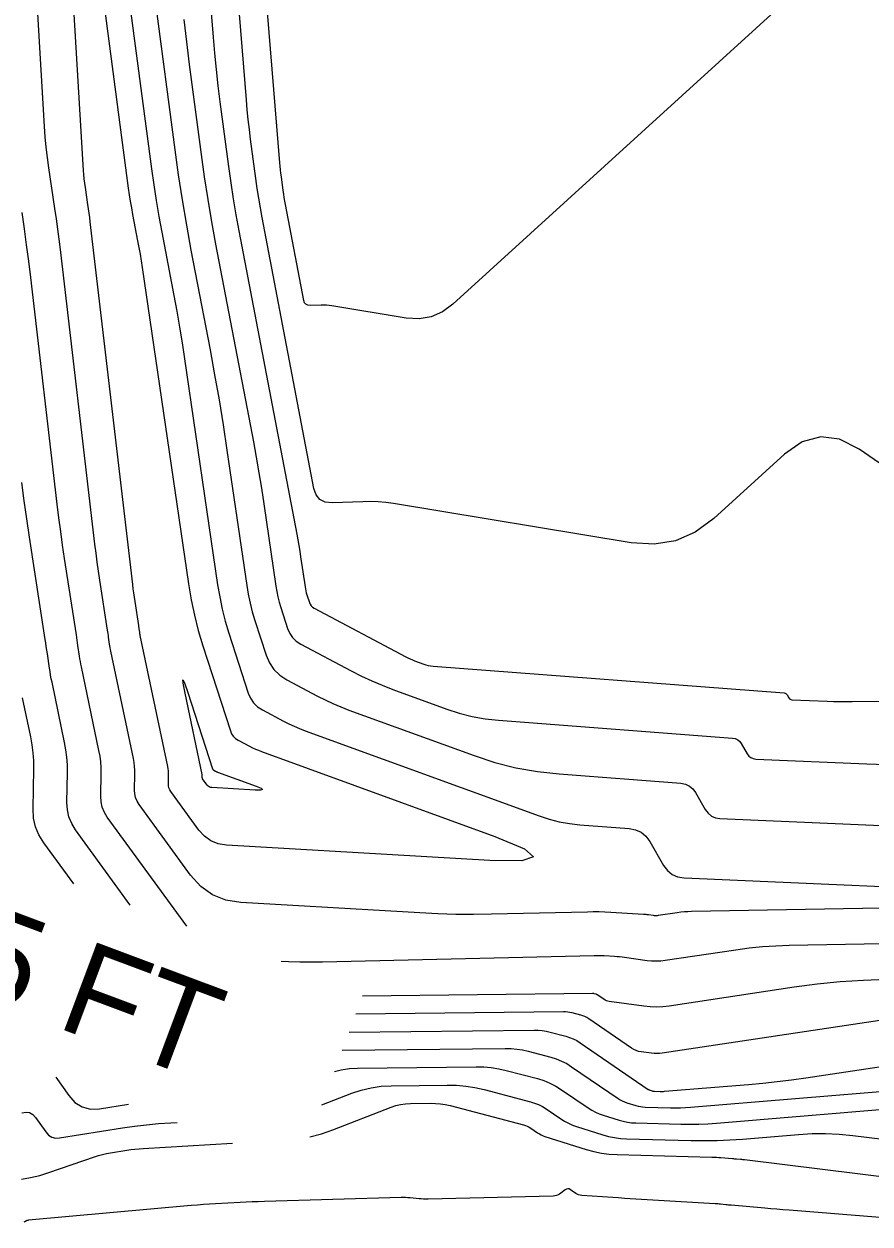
# Model space of a CAD drawing. Extents: x 1768942 to 1774819, y 723037 to 732099.
# Drawn here: x 1770893.1 to 1770947.3, y 724474.6 to 724551.5 of the extents above; entities that cross this region are included whole.
import ezdxf

# ---------------------------------------------------------------- set-up
doc = ezdxf.new("R2010")
doc.units = 0
doc.layers.add('R_Contour Annot', color=7, linetype='Continuous')
doc.layers.add('R_Contours', color=7, linetype='Continuous')

msp = doc.modelspace()

# ---------------------------------------------------------------- linework, layer by layer
at = {"layer": 'R_Contours'}
for points in [[(1770944.996, 724555.826), (1770920.559, 724533.556), (1770919.893, 724533.065), (1770919.175, 724532.754), (1770918.403, 724532.624), (1770917.577, 724532.674), (1770912.81, 724533.462), (1770912.637, 724533.486), (1770912.463, 724533.501), (1770912.289, 724533.508), (1770912.115, 724533.505), (1770911.416, 724533.479), (1770911.259, 724533.494), (1770911.137, 724533.555), (1770911.051, 724533.659), (1770911, 724533.809), (1770909.826, 724539.957), (1770909.786, 724540.179), (1770909.748, 724540.4), (1770909.714, 724540.623), (1770909.683, 724540.845), (1770909.565, 724541.738), (1770909.537, 724541.961), (1770909.512, 724542.184), (1770909.489, 724542.408), (1770909.469, 724542.632), (1770907.695, 724564.314)], [(1770962.968, 724513.006), (1770946.615, 724524.278), (1770945.369, 724524.91), (1770944.155, 724525.066), (1770942.974, 724524.747), (1770941.824, 724523.953), (1770937.292, 724519.822), (1770936.111, 724518.95), (1770934.836, 724518.398), (1770933.466, 724518.167), (1770932.001, 724518.257), (1770916.755, 724520.775), (1770916.267, 724520.843), (1770915.778, 724520.887), (1770915.287, 724520.905), (1770914.794, 724520.899), (1770912.82, 724520.823), (1770912.377, 724520.867), (1770912.034, 724521.037), (1770911.791, 724521.333), (1770911.648, 724521.756), (1770908.334, 724539.112), (1770908.219, 724539.736), (1770908.113, 724540.362), (1770908.017, 724540.99), (1770907.929, 724541.618), (1770907.596, 724544.137), (1770907.517, 724544.767), (1770907.445, 724545.398), (1770907.382, 724546.029), (1770907.326, 724546.662), (1770905.976, 724563.16)], [(1770904.257, 724562.006), (1770905.183, 724550.692), (1770905.275, 724549.651), (1770905.379, 724548.611), (1770905.497, 724547.573), (1770905.627, 724546.536), (1770906.175, 724542.391), (1770906.319, 724541.356), (1770906.478, 724540.324), (1770906.652, 724539.294), (1770906.841, 724538.266), (1770910.556, 724518.816), (1770910.623, 724518.453), (1770910.686, 724518.091), (1770910.745, 724517.727), (1770910.801, 724517.363), (1770911.084, 724515.432), (1770911.105, 724515.305), (1770911.131, 724515.179), (1770911.163, 724515.055), (1770911.2, 724514.932), (1770911.359, 724514.442), (1770911.407, 724514.327), (1770911.475, 724514.228), (1770911.561, 724514.144), (1770911.665, 724514.076), (1770917.546, 724510.953), (1770917.684, 724510.883), (1770917.824, 724510.818), (1770917.966, 724510.758), (1770918.11, 724510.703), (1770918.692, 724510.491), (1770918.838, 724510.443), (1770918.987, 724510.406), (1770919.138, 724510.379), (1770919.291, 724510.362), (1770941.82, 724508.634), (1770941.876, 724508.623), (1770941.924, 724508.601), (1770941.965, 724508.567), (1770941.998, 724508.521), (1770942.117, 724508.313), (1770942.151, 724508.268), (1770942.192, 724508.234), (1770942.24, 724508.213), (1770942.296, 724508.205), (1770944.567, 724508.107), (1770944.965, 724508.092), (1770945.364, 724508.083), (1770945.763, 724508.079), (1770946.161, 724508.081), (1770964.2, 724508.274)], [(1770897.085, 724561.182), (1770899.75, 724541.013), (1770899.81, 724540.586), (1770899.875, 724540.161), (1770899.947, 724539.736), (1770900.025, 724539.312), (1770900.348, 724537.62), (1770900.426, 724537.196), (1770900.5, 724536.772), (1770900.57, 724536.347), (1770900.634, 724535.921), (1770903.607, 724515.624), (1770903.776, 724514.616), (1770903.987, 724513.618), (1770904.24, 724512.63), (1770904.533, 724511.651), (1770906.294, 724506.203), (1770906.373, 724506.018), (1770906.482, 724505.858), (1770906.621, 724505.722), (1770906.789, 724505.612), (1770907.525, 724505.222), (1770907.71, 724505.127), (1770907.898, 724505.04), (1770908.09, 724504.959), (1770908.284, 724504.884), (1770923.25, 724499.44), (1770925.149, 724498.645), (1770925.729, 724498.123), (1770924.99, 724497.873), (1770922.931, 724497.895), (1770906.04, 724498.88), (1770905.514, 724498.965), (1770905.045, 724499.153), (1770904.633, 724499.446), (1770904.277, 724499.843), (1770902.479, 724502.313), (1770902.408, 724502.428), (1770902.358, 724502.549), (1770902.329, 724502.678), (1770902.321, 724502.813), (1770902.331, 724503.366), (1770902.33, 724503.504), (1770902.321, 724503.641), (1770902.304, 724503.778), (1770902.279, 724503.913), (1770900.517, 724512.319), (1770900.507, 724512.372), (1770900.497, 724512.426), (1770900.488, 724512.479), (1770900.479, 724512.533), (1770900.448, 724512.749), (1770900.44, 724512.803), (1770900.432, 724512.857), (1770900.424, 724512.91), (1770900.415, 724512.964), (1770900.179, 724514.499), (1770900.138, 724514.773), (1770900.099, 724515.047), (1770900.064, 724515.321), (1770900.03, 724515.596), (1770897.308, 724538.849), (1770897.275, 724539.124), (1770897.239, 724539.399), (1770897.201, 724539.674), (1770897.161, 724539.948), (1770896.995, 724541.045), (1770896.956, 724541.319), (1770896.924, 724541.594), (1770896.898, 724541.87), (1770896.879, 724542.146), (1770895.708, 724561.836)], [(1770952.924, 724494.92), (1770935.868, 724494.619), (1770935.638, 724494.611), (1770935.408, 724494.595), (1770935.179, 724494.572), (1770934.95, 724494.542), (1770933.738, 724494.36), (1770933.659, 724494.351), (1770933.581, 724494.348), (1770933.502, 724494.35), (1770933.423, 724494.358), (1770933.108, 724494.402), (1770933.029, 724494.412), (1770932.95, 724494.421), (1770932.871, 724494.428), (1770932.791, 724494.434), (1770930.694, 724494.561), (1770930.318, 724494.58), (1770929.942, 724494.591), (1770929.565, 724494.594), (1770929.189, 724494.589), (1770923.044, 724494.446), (1770921.894, 724494.43), (1770920.745, 724494.439), (1770919.597, 724494.47), (1770918.448, 724494.526), (1770906.975, 724495.195), (1770906.01, 724495.35), (1770905.149, 724495.696), (1770904.393, 724496.233), (1770903.741, 724496.961), (1770900.442, 724501.492), (1770900.312, 724501.704), (1770900.22, 724501.927), (1770900.167, 724502.163), (1770900.152, 724502.41), (1770900.17, 724503.425), (1770900.167, 724503.678), (1770900.151, 724503.93), (1770900.12, 724504.18), (1770900.075, 724504.43), (1770898.631, 724511.318), (1770898.608, 724511.43), (1770898.588, 724511.541), (1770898.569, 724511.654), (1770898.551, 724511.766), (1770898.485, 724512.217), (1770898.469, 724512.329), (1770898.452, 724512.442), (1770898.435, 724512.555), (1770898.418, 724512.667), (1770897.923, 724515.874), (1770897.838, 724516.446), (1770897.758, 724517.019), (1770897.682, 724517.593), (1770897.613, 724518.167), (1770895.4, 724537.067), (1770895.32, 724537.725), (1770895.235, 724538.383), (1770895.144, 724539.039), (1770895.048, 724539.695), (1770894.651, 724542.317), (1770894.559, 724542.974), (1770894.482, 724543.631), (1770894.42, 724544.291), (1770894.373, 724544.952), (1770893.488, 724559.836)], [(1770899.278, 724557.086), (1770901.239, 724542.242), (1770901.382, 724541.221), (1770901.539, 724540.204), (1770901.71, 724539.188), (1770901.896, 724538.175), (1770902.669, 724534.127), (1770902.857, 724533.114), (1770903.034, 724532.099), (1770903.199, 724531.083), (1770903.354, 724530.064), (1770905.476, 724515.576), (1770905.609, 724514.789), (1770905.773, 724514.009), (1770905.97, 724513.236), (1770906.2, 724512.471), (1770907.441, 724508.631), (1770907.586, 724508.291), (1770907.786, 724507.997), (1770908.041, 724507.749), (1770908.35, 724507.547), (1770909.7, 724506.83), (1770910.04, 724506.657), (1770910.385, 724506.496), (1770910.736, 724506.347), (1770911.092, 724506.211), (1770926.095, 724500.753), (1770926.735, 724500.545), (1770927.384, 724500.381), (1770928.043, 724500.262), (1770928.711, 724500.188), (1770931.871, 724499.946), (1770932.284, 724499.868), (1770932.642, 724499.704), (1770932.944, 724499.451), (1770933.192, 724499.112), (1770934.071, 724497.579), (1770934.318, 724497.241), (1770934.621, 724496.995), (1770934.98, 724496.839), (1770935.393, 724496.775), (1770957.86, 724495.806)], [(1770901.471, 724552.99), (1770902.729, 724543.47), (1770902.954, 724541.856), (1770903.202, 724540.246), (1770903.473, 724538.64), (1770903.767, 724537.037), (1770904.99, 724530.634), (1770905.287, 724529.032), (1770905.567, 724527.427), (1770905.829, 724525.819), (1770906.074, 724524.208), (1770907.346, 724515.528), (1770907.441, 724514.961), (1770907.559, 724514.399), (1770907.701, 724513.842), (1770907.867, 724513.291), (1770908.588, 724511.06), (1770908.799, 724510.564), (1770909.09, 724510.136), (1770909.461, 724509.775), (1770909.911, 724509.481), (1770911.874, 724508.439), (1770912.369, 724508.187), (1770912.872, 724507.953), (1770913.382, 724507.736), (1770913.9, 724507.538), (1770921.921, 724504.62), (1770923.256, 724504.185), (1770924.611, 724503.843), (1770925.986, 724503.595), (1770927.381, 724503.441), (1770935.187, 724502.842), (1770935.481, 724502.787), (1770935.736, 724502.669), (1770935.951, 724502.49), (1770936.127, 724502.248), (1770936.753, 724501.157), (1770936.929, 724500.917), (1770937.145, 724500.741), (1770937.4, 724500.631), (1770937.694, 724500.585), (1770951.996, 724499.968)], [(1770903.313, 724551.825), (1770903.477, 724550.379), (1770903.658, 724548.935), (1770904.421, 724543.165), (1770904.622, 724541.723), (1770904.843, 724540.286), (1770905.086, 724538.851), (1770905.348, 724537.42), (1770907.77, 724524.743), (1770907.953, 724523.752), (1770908.126, 724522.759), (1770908.289, 724521.764), (1770908.44, 724520.767), (1770909.215, 724515.48), (1770909.273, 724515.133), (1770909.345, 724514.789), (1770909.432, 724514.449), (1770909.533, 724514.112), (1770909.967, 724512.77), (1770910.101, 724512.456), (1770910.285, 724512.184), (1770910.52, 724511.955), (1770910.806, 724511.769), (1770914.049, 724510.047), (1770914.699, 724509.717), (1770915.358, 724509.409), (1770916.028, 724509.125), (1770916.709, 724508.864), (1770920.167, 724507.606), (1770920.978, 724507.342), (1770921.801, 724507.134), (1770922.636, 724506.984), (1770923.484, 724506.89), (1770938.504, 724505.738), (1770938.678, 724505.705), (1770938.83, 724505.635), (1770938.958, 724505.528), (1770939.063, 724505.385), (1770939.435, 724504.735), (1770939.54, 724504.592), (1770939.668, 724504.488), (1770939.82, 724504.422), (1770939.995, 724504.395), (1770947.102, 724504.088), (1770948.349, 724504.043)], [(1770903.495, 724493.68), (1770898.404, 724500.672), (1770898.215, 724500.979), (1770898.082, 724501.305), (1770898.004, 724501.647), (1770897.983, 724502.008), (1770898.009, 724503.484), (1770898.005, 724503.853), (1770897.981, 724504.219), (1770897.936, 724504.583), (1770897.87, 724504.946), (1770896.745, 724510.317), (1770896.71, 724510.487), (1770896.679, 724510.657), (1770896.65, 724510.828), (1770896.623, 724510.999), (1770896.523, 724511.685), (1770896.498, 724511.856), (1770896.472, 724512.028), (1770896.446, 724512.199), (1770896.42, 724512.37), (1770895.668, 724517.249), (1770895.538, 724518.12), (1770895.416, 724518.992), (1770895.301, 724519.865), (1770895.195, 724520.739), (1770893.492, 724535.285), (1770893.366, 724536.326), (1770893.231, 724537.366), (1770893.087, 724538.405), (1770892.934, 724539.442)], [(1770899.874, 724495.035), (1770896.367, 724499.852), (1770896.119, 724500.255), (1770895.943, 724500.682), (1770895.842, 724501.132), (1770895.814, 724501.605), (1770895.848, 724503.544), (1770895.843, 724504.027), (1770895.811, 724504.508), (1770895.752, 724504.986), (1770895.666, 724505.462), (1770894.858, 724509.317), (1770894.812, 724509.545), (1770894.77, 724509.773), (1770894.731, 724510.002), (1770894.695, 724510.232), (1770894.56, 724511.153), (1770894.526, 724511.383), (1770894.492, 724511.613), (1770894.457, 724511.843), (1770894.422, 724512.073), (1770893.413, 724518.624), (1770893.238, 724519.794), (1770893.074, 724520.964), (1770892.92, 724522.136)], [(1770896.253, 724496.39), (1770894.33, 724499.032), (1770894.022, 724499.531), (1770893.805, 724500.06), (1770893.679, 724500.617), (1770893.644, 724501.202), (1770893.69, 724503.76), (1770893.684, 724504.28), (1770893.65, 724504.798), (1770893.586, 724505.312), (1770893.494, 724505.824), (1770892.972, 724508.316)], [(1770954.156, 724492.65), (1770942.124, 724492.437), (1770941.266, 724492.408), (1770940.41, 724492.351), (1770939.556, 724492.265), (1770938.704, 724492.151), (1770934.188, 724491.473), (1770933.895, 724491.44), (1770933.602, 724491.428), (1770933.308, 724491.437), (1770933.015, 724491.467), (1770931.576, 724491.668), (1770931.414, 724491.689), (1770931.252, 724491.706), (1770931.09, 724491.721), (1770930.927, 724491.733), (1770930.275, 724491.772), (1770930.112, 724491.78), (1770929.949, 724491.785), (1770929.786, 724491.786), (1770929.623, 724491.784), (1770912.208, 724491.377), (1770911.481, 724491.368), (1770910.755, 724491.373), (1770910.029, 724491.393), (1770909.544, 724491.416)], [(1770948.381, 724490.256), (1770946.894, 724490.206), (1770945.411, 724490.106), (1770943.933, 724489.958), (1770942.458, 724489.761), (1770934.427, 724488.555), (1770934.025, 724488.509), (1770933.623, 724488.492), (1770933.22, 724488.505), (1770932.818, 724488.546), (1770930.59, 724488.857), (1770930.498, 724488.875), (1770930.411, 724488.903), (1770930.327, 724488.941), (1770930.248, 724488.99), (1770929.826, 724489.278), (1770929.803, 724489.292), (1770929.779, 724489.305), (1770929.754, 724489.315), (1770929.728, 724489.323), (1770929.623, 724489.35), (1770929.596, 724489.356), (1770929.57, 724489.36), (1770929.543, 724489.363), (1770929.516, 724489.363), (1770914.772, 724489.199)], [(1770948.368, 724487.695), (1770933.978, 724485.533), (1770933.811, 724485.514), (1770933.644, 724485.507), (1770933.477, 724485.512), (1770933.31, 724485.529), (1770932.642, 724485.623), (1770932.478, 724485.655), (1770932.321, 724485.705), (1770932.172, 724485.773), (1770932.029, 724485.86), (1770929.277, 724487.742), (1770929.156, 724487.817), (1770929.031, 724487.881), (1770928.9, 724487.934), (1770928.765, 724487.976), (1770928.212, 724488.12), (1770928.074, 724488.151), (1770927.934, 724488.173), (1770927.793, 724488.186), (1770927.651, 724488.189), (1770914.339, 724488.041)], [(1770913.905, 724486.882), (1770925.785, 724487.015), (1770926.043, 724487.009), (1770926.298, 724486.986), (1770926.551, 724486.947), (1770926.802, 724486.89), (1770927.801, 724486.628), (1770928.047, 724486.553), (1770928.283, 724486.458), (1770928.51, 724486.342), (1770928.727, 724486.206), (1770933.099, 724483.216), (1770933.128, 724483.198), (1770933.158, 724483.182), (1770933.189, 724483.169), (1770933.221, 724483.157), (1770933.351, 724483.116), (1770933.384, 724483.107), (1770933.418, 724483.1), (1770933.451, 724483.096), (1770933.485, 724483.094), (1770933.853, 724483.084), (1770933.926, 724483.083), (1770933.998, 724483.084), (1770934.071, 724483.087), (1770934.143, 724483.092), (1770939.526, 724483.537), (1770940.447, 724483.62), (1770941.365, 724483.72), (1770942.282, 724483.834), (1770943.197, 724483.964), (1770954.598, 724485.676)], [(1770913.472, 724485.724), (1770923.92, 724485.84), (1770924.292, 724485.832), (1770924.662, 724485.799), (1770925.028, 724485.742), (1770925.391, 724485.66), (1770926.838, 724485.281), (1770927.193, 724485.172), (1770927.535, 724485.034), (1770927.863, 724484.867), (1770928.178, 724484.67), (1770931.17, 724482.624), (1770931.298, 724482.543), (1770931.431, 724482.473), (1770931.569, 724482.412), (1770931.711, 724482.361), (1770932.292, 724482.178), (1770932.438, 724482.138), (1770932.586, 724482.108), (1770932.735, 724482.088), (1770932.887, 724482.079), (1770934.521, 724482.035), (1770934.844, 724482.031), (1770935.166, 724482.036), (1770935.489, 724482.049), (1770935.811, 724482.072), (1770956.013, 724483.74)], [(1770912.965, 724484.37), (1770913.406, 724484.476), (1770913.928, 724484.552), (1770914.458, 724484.581), (1770922.055, 724484.666), (1770922.542, 724484.655), (1770923.026, 724484.612), (1770923.505, 724484.537), (1770923.981, 724484.429), (1770925.982, 724483.906), (1770926.394, 724483.78), (1770926.791, 724483.619), (1770927.172, 724483.425), (1770927.538, 724483.197), (1770929.241, 724482.032), (1770929.468, 724481.888), (1770929.704, 724481.763), (1770929.949, 724481.655), (1770930.202, 724481.565), (1770931.233, 724481.24), (1770931.492, 724481.168), (1770931.754, 724481.115), (1770932.02, 724481.08), (1770932.288, 724481.064), (1770935.189, 724480.987), (1770935.762, 724480.98), (1770936.334, 724480.988), (1770936.907, 724481.012), (1770937.479, 724481.051), (1770948.457, 724481.958)], [(1770895.104, 724484.007), (1770895.934, 724482.819), (1770896.33, 724482.377), (1770896.791, 724482.089), (1770897.318, 724481.956), (1770897.911, 724481.978), (1770899.754, 724482.267)], [(1770912.161, 724482.221), (1770914.074, 724482.963), (1770914.691, 724483.171), (1770915.319, 724483.322), (1770915.958, 724483.416), (1770916.608, 724483.452), (1770920.19, 724483.492), (1770920.792, 724483.479), (1770921.39, 724483.425), (1770921.982, 724483.332), (1770922.57, 724483.199), (1770925.533, 724482.424), (1770925.802, 724482.342), (1770926.061, 724482.237), (1770926.31, 724482.11), (1770926.549, 724481.961), (1770927.485, 724481.322), (1770927.723, 724481.171), (1770927.97, 724481.039), (1770928.227, 724480.926), (1770928.493, 724480.831), (1770930.173, 724480.302), (1770930.546, 724480.199), (1770930.923, 724480.122), (1770931.304, 724480.072), (1770931.69, 724480.049), (1770935.856, 724479.938), (1770936.68, 724479.928), (1770937.503, 724479.94), (1770938.325, 724479.974), (1770939.146, 724480.031), (1770942.729, 724480.327), (1770943.6, 724480.376), (1770944.469, 724480.381), (1770945.338, 724480.342), (1770946.206, 724480.258), (1770955.467, 724479.122)], [(1770911.396, 724480.178), (1770912.129, 724480.368), (1770912.859, 724480.619), (1770916.607, 724482.073), (1770916.909, 724482.175), (1770917.215, 724482.249), (1770917.527, 724482.294), (1770917.845, 724482.312), (1770919.125, 724482.326), (1770919.444, 724482.319), (1770919.76, 724482.291), (1770920.074, 724482.242), (1770920.385, 724482.172), (1770925.085, 724480.943), (1770925.211, 724480.904), (1770925.332, 724480.855), (1770925.449, 724480.796), (1770925.561, 724480.726), (1770925.999, 724480.426), (1770926.111, 724480.356), (1770926.226, 724480.294), (1770926.347, 724480.241), (1770926.471, 724480.197), (1770929.114, 724479.364), (1770929.6, 724479.23), (1770930.091, 724479.13), (1770930.588, 724479.064), (1770931.091, 724479.033), (1770937.178, 724478.873), (1770937.322, 724478.868), (1770937.467, 724478.861), (1770937.611, 724478.852), (1770937.756, 724478.841), (1770938.495, 724478.78), (1770938.558, 724478.775), (1770938.622, 724478.77), (1770938.685, 724478.765), (1770938.749, 724478.759), (1770939.002, 724478.739), (1770939.066, 724478.733), (1770939.129, 724478.727), (1770939.193, 724478.72), (1770939.256, 724478.713), (1770954.112, 724476.891)], [(1770892.93, 724481.718), (1770893.189, 724481.763), (1770893.42, 724481.729), (1770893.625, 724481.615), (1770893.802, 724481.421), (1770894.456, 724480.485), (1770894.634, 724480.286), (1770894.842, 724480.157), (1770895.079, 724480.097), (1770895.347, 724480.106), (1770899.385, 724480.741), (1770900.153, 724480.853), (1770900.923, 724480.945), (1770901.695, 724481.019), (1770902.469, 724481.074), (1770902.88, 724481.098)], [(1770892.89, 724477.453), (1770893.482, 724477.558), (1770894.067, 724477.701), (1770894.643, 724477.88), (1770897.578, 724478.895), (1770897.83, 724478.975), (1770898.085, 724479.045), (1770898.342, 724479.103), (1770898.603, 724479.15), (1770899.651, 724479.315), (1770899.913, 724479.353), (1770900.176, 724479.384), (1770900.439, 724479.41), (1770900.704, 724479.428), (1770906.44, 724479.765)], [(1770952.996, 724474.584), (1770942.122, 724475.467), (1770941.733, 724475.498), (1770941.344, 724475.531), (1770940.956, 724475.563), (1770940.567, 724475.597), (1770938.405, 724475.783), (1770938.32, 724475.79), (1770938.235, 724475.799), (1770938.15, 724475.807), (1770938.065, 724475.816), (1770937.725, 724475.854), (1770937.64, 724475.863), (1770937.555, 724475.871), (1770937.47, 724475.878), (1770937.385, 724475.883), (1770932.297, 724476.183), (1770931.928, 724476.206), (1770931.56, 724476.229), (1770931.192, 724476.252), (1770930.825, 724476.277), (1770928.827, 724476.413), (1770928.724, 724476.427), (1770928.626, 724476.453), (1770928.533, 724476.493), (1770928.444, 724476.546), (1770928.098, 724476.785), (1770928.012, 724476.829), (1770927.927, 724476.843), (1770927.842, 724476.826), (1770927.758, 724476.778), (1770927.398, 724476.507), (1770927.307, 724476.449), (1770927.211, 724476.406), (1770927.11, 724476.38), (1770927.002, 724476.369), (1770918.971, 724476.185), (1770918.827, 724476.183), (1770918.684, 724476.186), (1770918.54, 724476.193), (1770918.397, 724476.204), (1770917.823, 724476.255), (1770917.679, 724476.266), (1770917.536, 724476.273), (1770917.392, 724476.275), (1770917.248, 724476.273), (1770908.479, 724476.025), (1770908.088, 724476.012), (1770907.696, 724475.998), (1770907.305, 724475.981), (1770906.914, 724475.961), (1770905.35, 724475.878), (1770904.959, 724475.856), (1770904.569, 724475.829), (1770904.178, 724475.8), (1770903.788, 724475.766), (1770893.34, 724474.822), (1770893.309, 724474.817), (1770893.279, 724474.81), (1770893.251, 724474.8), (1770893.223, 724474.786), (1770893.113, 724474.727), (1770893.086, 724474.714), (1770893.057, 724474.705)]]:
    msp.add_lwpolyline(points, dxfattribs=at)
msp.add_lwpolyline([(1770904.492, 724503.33), (1770904.49, 724503.352), (1770904.488, 724503.375), (1770904.484, 724503.397), (1770903.39, 724508.616), (1770903.267, 724509.256), (1770903.256, 724509.477), (1770903.356, 724509.279), (1770903.567, 724508.663), (1770905.147, 724503.775), (1770905.16, 724503.745), (1770905.178, 724503.718), (1770905.201, 724503.696), (1770905.229, 724503.678), (1770905.35, 724503.613), (1770905.381, 724503.598), (1770905.412, 724503.583), (1770905.443, 724503.57), (1770905.475, 724503.558), (1770907.947, 724502.658), (1770908.261, 724502.527), (1770908.357, 724502.441), (1770908.235, 724502.399), (1770907.895, 724502.403), (1770905.105, 724502.566), (1770905.018, 724502.58), (1770904.94, 724502.611), (1770904.872, 724502.659), (1770904.814, 724502.725), (1770904.517, 724503.133), (1770904.505, 724503.152), (1770904.497, 724503.172), (1770904.492, 724503.193), (1770904.49, 724503.215), (1770904.492, 724503.307)], close=True, dxfattribs=at)

# ---------------------------------------------------------------- texts
at = {"layer": 'R_Contour Annot'}
msp.add_text('285 FT', height=6, rotation=339.48369, dxfattribs=at).set_placement((1770880.398, 724492.714))

doc.saveas('drawing.dxf')
